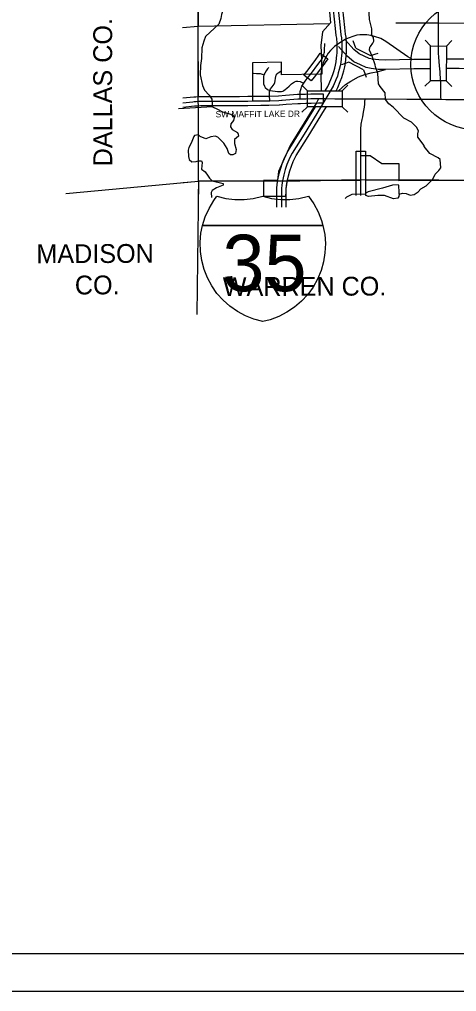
# Model space of a CAD drawing. Extents: x -1403959 to 81668, y -1400582 to 11018.
# Drawn here: x 6223 to 6493, y 7241 to 7841 of the extents above; entities that cross this region are included whole.
import ezdxf

# ---------------------------------------------------------------- set-up
doc = ezdxf.new("R2010")
doc.units = 0
for name, color, linetype in [('tdCiAirportTxt', 7, 'Continuous'), ('tdCiCityCartoShort', 7, 'Continuous'), ('tdCiCityStreetTxt', 7, 'Continuous'), ('tdCiCoBndryTxt', 7, 'Continuous'), ('tdCiRRCL', 7, 'Continuous'), ('tdCiRROwnerTxt', 7, 'Continuous'), ('tdCiSectLine', 7, 'Continuous'), ('tdCiSectNmbr', 7, 'Continuous'), ('tdCiSectTwpRng', 7, 'Continuous'), ('tdCoCityStreetMajor', 7, 'Continuous'), ('tdCoCityStreetMinor', 7, 'Continuous'), ('tdCoClipBndry', 7, 'Continuous'), ('tdCoDivCarto', 7, 'Continuous'), ('tdCoPriCL', 7, 'Continuous'), ('tdCoSecRdNmbr', 7, 'Continuous'), ('tdCoSectLine', 7, 'Continuous'), ('tdCoSectNmbr', 7, 'Continuous'), ('tdCoSurfAsphalt', 7, 'Continuous'), ('tdCoSurfBitum', 7, 'Continuous'), ('tdCoSurfEarth', 7, 'Continuous'), ('tdCoSurfGravel', 7, 'Continuous')]:
    doc.layers.add(name, color=color, linetype=linetype)

msp = doc.modelspace()

# ---------------------------------------------------------------- linework, layer by layer
at = {"layer": 'tdCiAirportTxt'}
for points in [[(6411.84, 7796.77), (6413.48, 7799.47), (6414.4, 7801.3), (6415.87, 7804.73), (6416.69, 7806.83), (6417.22, 7808.66), (6417.82, 7810.71), (6418.3, 7812.72), (6418.62, 7814.76), (6418.88, 7816.87), (6419.16, 7818.84), (6419.21, 7820.13), (6419.24, 7821.55), (6419.23, 7822.21), (6419.34, 7826.04), (6419.01, 7829.21), (6418.78, 7830.96), (6418.29, 7835.25), (6415.77, 7858.39)], [(6418.61, 7796.78), (6419.66, 7798.84), (6421.24, 7802.53), (6422.19, 7804.96), (6422.8, 7807.05), (6423.43, 7809.22), (6424, 7811.6), (6424.37, 7813.95), (6424.64, 7816.1), (6424.95, 7818.32), (6425.01, 7819.97), (6425.04, 7821.52), (6425.04, 7822.14), (6425.15, 7826.26), (6424.78, 7829.89), (6424.54, 7831.67), (6424.06, 7835.89), (6421.54, 7859)], [(6382.03, 7725.01), (6382.03, 7733.47), (6382.13, 7736.79), (6382.33, 7739.11), (6382.79, 7741.85), (6383.57, 7745.77), (6384.5, 7749.2), (6385.63, 7752.51), (6386.91, 7755.53), (6387.79, 7757.47), (6389.06, 7759.88), (6396.39, 7771.64), (6405.88, 7787.02)], [(6387.84, 7725), (6387.84, 7733.38), (6387.93, 7736.45), (6388.1, 7738.39), (6388.5, 7740.81), (6389.22, 7744.44), (6390.05, 7747.5), (6391.05, 7750.43), (6392.22, 7753.19), (6393.01, 7754.91), (6394.1, 7756.99), (6401.32, 7768.58), (6411.48, 7785.03), (6412.68, 7787.03)]]:
    msp.add_lwpolyline(points, dxfattribs=at)
at = {"layer": 'tdCiCityCartoShort'}
for points in [[(6418.65, 7858.67), (6421.18, 7835.55), (6421.66, 7831.29), (6421.9, 7829.53), (6422.25, 7826.13), (6422.13, 7822.15), (6422.14, 7821.51), (6422.11, 7820.03), (6422.06, 7818.56), (6421.76, 7816.46), (6421.49, 7814.33), (6421.15, 7812.14), (6420.62, 7809.94), (6420.01, 7807.83), (6419.44, 7805.87), (6418.55, 7803.61), (6417.03, 7800.04), (6415.48, 7796.99)], [(6416.87, 7799.6), (6409, 7786.52), (6398.85, 7770.09), (6391.58, 7758.41), (6390.4, 7756.16), (6389.57, 7754.33), (6388.34, 7751.45), (6387.27, 7748.33), (6386.39, 7745.08), (6385.64, 7741.31), (6385.21, 7738.73), (6385.03, 7736.6), (6384.93, 7733.4), (6384.93, 7727.88), (6384.93, 7724.98)]]:
    msp.add_lwpolyline(points, dxfattribs=at)
at = {"layer": 'tdCiCityStreetTxt'}
for p, q in [((6476.92, 7824.5), (6473.49, 7827.96)), ((6476.79, 7803.05), (6476.92, 7824.5)), ((6476.92, 7824.5), (6486.66, 7824.44)), ((6486.66, 7824.44), (6486.53, 7802.99)), ((6486.66, 7824.44), (6490.13, 7827.86)), ((6400.94, 7796.76), (6397.49, 7800.2)), ((6422.38, 7796.78), (6425.83, 7800.23)), ((6476.79, 7803.05), (6473.32, 7799.63)), ((6486.53, 7802.99), (6476.79, 7803.05)), ((6486.53, 7802.99), (6486.53, 7802.99)), ((6486.53, 7802.99), (6489.96, 7799.53)), ((6400.94, 7796.76), (6422.38, 7796.78)), ((6400.95, 7787.01), (6400.94, 7796.76)), ((6422.38, 7796.78), (6422.39, 7787.04)), ((6400.95, 7787.01), (6397.5, 7783.56)), ((6422.39, 7787.04), (6400.95, 7787.01)), ((6400.95, 7787.01), (6400.95, 7787.01)), ((6422.39, 7787.04), (6425.84, 7783.59))]:
    msp.add_line(p, q, dxfattribs=at)
at = {"layer": 'tdCiCoBndryTxt'}
for points in [[(6324.01, 7789.48), (6330.3, 7790.09), (6331.09, 7790.16), (6332.35, 7790.27), (6333.61, 7790.35), (6333.71, 7790.35)], [(6333.71, 7790.35), (6333.72, 7790.35)], [(6333.72, 7790.35), (6334, 7790.36)], [(6334, 7790.36), (6334.87, 7790.38), (6340.71, 7790.38), (6348.1, 7790.37), (6359.01, 7790.48), (6364.2, 7790.53), (6367.1, 7790.54)], [(6367.1, 7790.54), (6372.12, 7790.57), (6377.07, 7790.61), (6377.79, 7790.64), (6383.41, 7790.88), (6387.7, 7791.31), (6395.02, 7791.77), (6395.3, 7791.77), (6396.56, 7791.77)], [(6433.9, 7741.86), (6433.87, 7748.92), (6433.88, 7756.72)]]:
    msp.add_lwpolyline(points, dxfattribs=at)
at = {"layer": 'tdCiRRCL'}
msp.add_line((6373.87, 7731.77), (6387.68, 7731.88), dxfattribs=at)
for points in [[(6411.41, 7879.71), (6415.21, 7838.79), (6410.32, 7833.22), (6409.21, 7824.84), (6409.55, 7815.92), (6409.88, 7807.12), (6385.03, 7806.58), (6385.04, 7814.41), (6367.1, 7813.99), (6367.1, 7790.54), (6377.07, 7790.61), (6383.41, 7790.88), (6385.02, 7791.04), (6387.7, 7791.31), (6395.02, 7791.77), (6396.56, 7791.77), (6399.88, 7791.93), (6403.16, 7791.99), (6407.8, 7792), (6407.73, 7791.85), (6406.6, 7789.32), (6390.28, 7763.02), (6383.19, 7747), (6382.41, 7741.71), (6373.85, 7741.52), (6373.87, 7731.77)], [(6387.68, 7731.88), (6387.75, 7734.68), (6387.88, 7736.33), (6388.19, 7738.91), (6388.51, 7740.78), (6388.71, 7741.72), (6433.9, 7741.75), (6433.91, 7756.87), (6439.59, 7756.88), (6446.88, 7752.02), (6457.28, 7751.94), (6457.24, 7741.46), (6578.95, 7741.63), (6579.15, 7731.96)]]:
    msp.add_lwpolyline(points, dxfattribs=at)
at = {"layer": 'tdCiRROwnerTxt'}
for points in [[(6402.79, 7806.97), (6408.02, 7813.81), (6408.87, 7814.94), (6409.55, 7815.9)], [(6396.56, 7791.77), (6399.88, 7791.93), (6403.16, 7791.99), (6407.8, 7792)], [(6433.9, 7741.75), (6433.9, 7741.86)], [(6433.98, 7732.24), (6433.95, 7734.37), (6433.95, 7735.82), (6433.92, 7738.29), (6433.9, 7741.05), (6433.9, 7741.75)]]:
    msp.add_lwpolyline(points, dxfattribs=at)
at = {"layer": 'tdCiSectLine'}
for points in [[(6403.33, 7802.91), (6398.72, 7806.43), (6400.49, 7808.74), (6405.71, 7815.56), (6406.52, 7816.64), (6407.18, 7817.57), (6408.85, 7819.94), (6413.59, 7816.6), (6411.92, 7814.23), (6411.24, 7813.26), (6411.19, 7813.2), (6410.35, 7812.07), (6410.33, 7812.04), (6405.1, 7805.21), (6403.33, 7802.91)], [(6324.01, 7792.4), (6330.81, 7793.05), (6330.83, 7793.05), (6332.09, 7793.16), (6332.16, 7793.17), (6332.18, 7793.17), (6333.44, 7793.24), (6333.53, 7793.25), (6334.79, 7793.28), (6334.87, 7793.28), (6340.71, 7793.28), (6340.72, 7793.28), (6348.09, 7793.27), (6358.98, 7793.38), (6358.99, 7793.38), (6364.17, 7793.43), (6364.18, 7793.43), (6372.1, 7793.48), (6377, 7793.51), (6383.2, 7793.77), (6387.41, 7794.19), (6387.51, 7794.2), (6387.52, 7794.2), (6394.83, 7794.66), (6395.02, 7794.67), (6395.02, 7794.67), (6396.49, 7794.67), (6399.73, 7794.83), (6399.83, 7794.83), (6403.11, 7794.89), (6403.15, 7794.89), (6407.79, 7794.9), (6410.69, 7794.91), (6410.71, 7789.11), (6407.81, 7789.1), (6403.19, 7789.08), (6399.97, 7789.03), (6396.7, 7788.87), (6396.56, 7788.86), (6396.56, 7788.86), (6395.11, 7788.86), (6387.94, 7788.41), (6383.7, 7787.99), (6383.6, 7787.98), (6383.53, 7787.98), (6377.2, 7787.71), (6377.1, 7787.71), (6372.14, 7787.67), (6372.13, 7787.67), (6364.22, 7787.62), (6359.04, 7787.58), (6348.13, 7787.47), (6348.1, 7787.47), (6348.1, 7787.47), (6340.71, 7787.48), (6334.91, 7787.48), (6333.74, 7787.45), (6332.56, 7787.38), (6331.36, 7787.27), (6324.01, 7786.57)], [(6431.07, 7732.22), (6431.05, 7734.33), (6431.05, 7734.37), (6431.05, 7735.8), (6431.01, 7738.25), (6431.01, 7738.27), (6431, 7741.04), (6431, 7741.04), (6430.97, 7748.91), (6430.97, 7748.92), (6430.97, 7748.93), (6430.98, 7756.73), (6430.99, 7759.63), (6436.79, 7759.62), (6436.79, 7756.72), (6436.77, 7748.93), (6436.8, 7741.07), (6436.82, 7738.31), (6436.85, 7735.86), (6436.85, 7735.82), (6436.85, 7734.39), (6436.88, 7732.23)]]:
    msp.add_lwpolyline(points, dxfattribs=at)
at = {"layer": 'tdCiSectNmbr'}
for points in [[(6396.56, 7791.77), (6396.46, 7793.55), (6396.42, 7794.93), (6396.46, 7795.62), (6396.54, 7796.31), (6396.66, 7796.99), (6396.83, 7797.67), (6397.03, 7798.33), (6397.27, 7798.98), (6397.56, 7799.61), (6397.88, 7800.23), (6398.25, 7800.87), (6398.65, 7801.49), (6399.07, 7802.09), (6399.53, 7802.68), (6401.47, 7805.25), (6402.78, 7806.97)], [(6407.8, 7792), (6408.92, 7792.01), (6412.61, 7791.99), (6417.8, 7791.91), (6427.5, 7791.8), (6436.49, 7791.8), (6449.36, 7791.82), (6462.21, 7791.59), (6482.39, 7791.7), (6483.25, 7791.66)], [(6433.92, 7771.11), (6433.93, 7773.18), (6433.98, 7774.26), (6434.05, 7775.24), (6434.16, 7776.23), (6434.31, 7777.21), (6434.48, 7778.19), (6434.69, 7779.15), (6435.09, 7780.81), (6435.63, 7783.67), (6436.08, 7786.82), (6436.27, 7788.49), (6436.36, 7789.98), (6436.49, 7791.8)], [(6483.25, 7791.66), (6483.38, 7791.66), (6486.25, 7791.54), (6496.24, 7791.54), (6499.15, 7791.42), (6502.05, 7791.28), (6504.58, 7791.11), (6507.11, 7790.97), (6509.64, 7790.86), (6510.86, 7790.86), (6519.03, 7790.86), (6531.05, 7790.82)], [(6433.88, 7756.72), (6433.88, 7756.81), (6433.95, 7764.73), (6433.92, 7769.28), (6433.92, 7771.11)]]:
    msp.add_lwpolyline(points, dxfattribs=at)
at = {"layer": 'tdCiSectTwpRng'}
for points in [[(6481.89, 7838.74), (6481.59, 7875.18), (6481.59, 7883.85), (6481.72, 7885.37), (6481.93, 7886.6), (6482.36, 7887.98)], [(6455.56, 7838.77), (6460.76, 7838.76)], [(6460.76, 7838.76), (6481.89, 7838.74)], [(6482.05, 7817.62), (6481.87, 7819.98), (6481.9, 7838.64), (6481.89, 7838.74)], [(6481.89, 7838.74), (6536.74, 7838.59), (6539.26, 7838.58), (6548.54, 7838.57), (6559.78, 7838.56)], [(6409.56, 7815.91), (6409.63, 7816.02), (6410, 7816.62), (6410.34, 7817.25), (6410.64, 7817.9), (6410.89, 7818.56), (6411.11, 7819.24), (6411.28, 7819.93), (6411.42, 7820.62), (6411.51, 7821.33), (6411.55, 7821.84), (6411.6, 7825.97)], [(6482.89, 7807.09), (6482.78, 7808.6), (6482.48, 7812.26), (6482.05, 7817.62)], [(6377.17, 7811.28), (6376.4, 7810.29), (6375.59, 7809.21), (6374.71, 7807.69), (6374.16, 7806.62), (6373.96, 7805.49), (6373.8, 7803.99), (6373.78, 7802.63), (6373.94, 7801.18), (6374.41, 7799.78), (6374.89, 7798.94), (6376.27, 7797.69), (6377.8, 7797.08), (6379.42, 7796.79), (6380.98, 7796.56), (6382.55, 7796.38), (6383.73, 7796.36), (6384.93, 7796.45), (6385.74, 7796.65), (6386.45, 7796.99), (6387.24, 7797.53), (6388.22, 7798.42), (6389.64, 7799.62), (6391.16, 7801.05), (6392.3, 7801.91), (6393, 7802.29), (6394.02, 7802.68), (6395.04, 7802.77), (6396.58, 7802.61), (6397.35, 7802.23), (6398.65, 7801.49)], [(6367.38, 7807.64), (6367.6, 7807.63)], [(6367.6, 7807.63), (6369.47, 7807.53), (6371.76, 7807.42), (6372.96, 7807.15), (6374.16, 7806.62)], [(6377.79, 7790.64), (6377.6, 7793.65), (6377.53, 7796.17), (6377.61, 7796.65), (6377.8, 7797.08), (6378.19, 7798.05), (6379.14, 7799.25), (6379.8, 7800.03), (6380.53, 7801), (6380.89, 7801.91), (6381.15, 7802.87), (6381.21, 7804.55), (6381.37, 7805.55), (6381.77, 7806.54), (6382.23, 7807.19), (6382.97, 7807.99), (6384.53, 7808.98)], [(6483.38, 7791.66), (6483.34, 7792.87), (6483.32, 7796.9), (6483.33, 7800.43), (6483.26, 7802.31), (6482.9, 7807.01), (6482.89, 7807.09)]]:
    msp.add_lwpolyline(points, dxfattribs=at)
at = {"layer": 'tdCoCityStreetMajor'}
for points in [[(6333.98, 7900.91), (6333.65, 7836.58)], [(6323.98, 7835.81), (6333.65, 7836.58)], [(6333.65, 7836.58), (6414.8, 7838.36)], [(6333.68, 7793.24), (6333.65, 7836.58)], [(6333.72, 7741.13), (6333.68, 7787.43)], [(6324.24, 7740.24), (6333.72, 7741.13)], [(6333.72, 7741.13), (6333.6, 7731.49)], [(6333.72, 7741.13), (6396.34, 7741.37), (6421.98, 7741.74)], [(6436.77, 7741.9), (6457.21, 7741.82)]]:
    msp.add_lwpolyline(points, dxfattribs=at)
at = {"layer": 'tdCoCityStreetMinor'}
for points in [[(6252.02, 7733.46), (6333.72, 7741.13)], [(6333.72, 7741.13), (6332.76, 7658.95)], [(6436.77, 7741.9), (6457.21, 7741.82)]]:
    msp.add_lwpolyline(points, dxfattribs=at)
at = {"layer": 'tdCoClipBndry'}
msp.add_lwpolyline([(6772.45, 7982.6), (6773.16, 7838.81), (6797.35, 7838.44), (6797.21, 7788.96), (6796.4, 7741.34), (6748.6, 7741.24), (6723.92, 7741.45), (6627.16, 7741.7), (6530.1, 7741.53), (6433.87, 7741.91), (6421.98, 7741.74), (6396.34, 7741.37), (6333.72, 7741.13), (6333.65, 7836.58), (6334.16, 7936.62)], dxfattribs=at)
at = {"layer": 'tdCoDivCarto'}
for points in [[(6476.87, 7816.2), (6466.4, 7816.08), (6449.18, 7815.73), (6445.03, 7815.82), (6440.9, 7816.3), (6441.22, 7816.25), (6439.03, 7816.75), (6432.82, 7819.68), (6429.57, 7822.35), (6424.43, 7828.07)], [(6476.83, 7810.4), (6466.53, 7810.27), (6449.19, 7809.93), (6444.62, 7810.03), (6440.23, 7810.54), (6437.19, 7811.22), (6433.6, 7812.8), (6429.63, 7814.78), (6425.56, 7818.13), (6420.08, 7824.23)], [(6535.85, 7816.42), (6514.47, 7816.27), (6494.65, 7816.36), (6486.61, 7816.32)], [(6537.33, 7810.62), (6514.57, 7810.47), (6494.64, 7810.56), (6486.58, 7810.52)]]:
    msp.add_lwpolyline(points, dxfattribs=at)
at = {"layer": 'tdCoPriCL'}
for points in [[(6465.74, 7816.06), (6462.83, 7817.76), (6449.3, 7827.28), (6446.22, 7828.98), (6442.34, 7830.4), (6440.03, 7830.96), (6437.69, 7831.29), (6435.32, 7831.38), (6433.2, 7831.28), (6431.35, 7831.03), (6429.54, 7830.57), (6426.15, 7829.28), (6424.16, 7828.37), (6421.59, 7826.9)], [(6421.59, 7826.9), (6417.73, 7824.08), (6415.18, 7821.7), (6413.66, 7819.93), (6412.01, 7817.09), (6410.73, 7814.06), (6409.8, 7810.77), (6409.28, 7807.34), (6409.33, 7796.76)], [(6420.09, 7796.8), (6424.48, 7800.61), (6427.74, 7802.85), (6432.47, 7805.34), (6436.34, 7806.88), (6440.36, 7807.98), (6444.56, 7808.76), (6449.19, 7809.93)]]:
    msp.add_lwpolyline(points, dxfattribs=at)
at = {"layer": 'tdCoSectLine'}
for points in [[(5665.9, 10336.72), (9631.74, 10336.72), (9631.74, 7241.43), (5665.9, 7241.43)], [(5689.11, 10313.51), (9608.52, 10313.51), (9608.52, 7264.65), (5689.11, 7264.65)]]:
    msp.add_lwpolyline(points, close=True, dxfattribs=at)
at = {"layer": 'tdCoSurfAsphalt'}
msp.add_circle((6505.12, 7813.11), 40.33, dxfattribs=at)
at = {"layer": 'tdCoSurfBitum'}
for points in [[(6457.47, 7733.16), (6459.61, 7733.61), (6461.9, 7733.45), (6464.34, 7732.52), (6466.79, 7732.82), (6469.24, 7734.49), (6470.93, 7736.47), (6474.14, 7738.14), (6478.28, 7742.24), (6479.82, 7745.45), (6481.96, 7747.73), (6483.19, 7749.25), (6482.75, 7754.44), (6481.68, 7755.52), (6476.5, 7758.13), (6473, 7762.57), (6473, 7763.03), (6469.05, 7768.24), (6469.06, 7770.37), (6469.52, 7772.05), (6468.31, 7774.5), (6465.11, 7777.57), (6460.39, 7779.87), (6453.84, 7786.77), (6451.25, 7788.76), (6449.12, 7791.37), (6448.99, 7795.49), (6445.79, 7799.47), (6444.88, 7801.16), (6444.29, 7807.57), (6442.93, 7811.55), (6442.78, 7812.92), (6440.97, 7818.27), (6439.3, 7821.79), (6439.46, 7823.77), (6439.92, 7824.08), (6441.3, 7826.21), (6441.92, 7827.43), (6441.77, 7829.72), (6440.71, 7831.1), (6440.72, 7835.07), (6439.22, 7840.72), (6438.22, 7861.04)], [(6351.13, 7850.52), (6349.59, 7849.15), (6347.89, 7843.97), (6347.58, 7841.37), (6346.35, 7837.86), (6338.07, 7830.26), (6336.99, 7827.52), (6335.91, 7823.24), (6335.58, 7816.68), (6334.95, 7812.41), (6334.78, 7806.6), (6336.13, 7800.03), (6337.5, 7797.28), (6340.39, 7794.06), (6341.91, 7791.61), (6342.35, 7787.03)], [(6342.35, 7787.03), (6321.46, 7785.79)], [(6342.35, 7787.03), (6345.55, 7785.49), (6348.6, 7783.8), (6353.79, 7782.41), (6355.01, 7781.64), (6355.77, 7780.42), (6355.3, 7778.58), (6353.77, 7776.45), (6353.45, 7774.62), (6354.52, 7772.94), (6357.72, 7771.09), (6358.33, 7770.18), (6358.48, 7768.95), (6356.02, 7766.82), (6356.02, 7764.23), (6356.92, 7760.56), (6356.6, 7758.12), (6354.92, 7757.36), (6353.55, 7757.37), (6352.48, 7758.13), (6351.42, 7761.34), (6349.45, 7764.56), (6345.64, 7768.24), (6343.97, 7768.85), (6341.37, 7768.41), (6338.31, 7767.2), (6334.8, 7768.74), (6333.74, 7769.66), (6331.29, 7769.21), (6330.83, 7768.6), (6329.29, 7764.48), (6327.9, 7761.89), (6327.29, 7760.21), (6327.58, 7756.24), (6328.03, 7754.41), (6329.55, 7753.03), (6332.3, 7753.17), (6333.53, 7753.62), (6335.51, 7753.62), (6335.97, 7752.55), (6335.65, 7748.42), (6337.93, 7746.89), (6339.76, 7744.29), (6340.51, 7742.91), (6342.19, 7741.38), (6348.9, 7739.67), (6348.9, 7738.6), (6344.77, 7736.94), (6342.17, 7735.42), (6341.55, 7734.2), (6341.68, 7730.95)], [(6453.52, 7738.67), (6447.25, 7736.71), (6438.39, 7734.45), (6437.16, 7733.85), (6436.85, 7733.08)], [(6457.47, 7733.16), (6457.63, 7734.38), (6457.34, 7738.35), (6456.88, 7738.81), (6453.52, 7738.67)], [(6436.85, 7733.08), (6428.45, 7732.81), (6425.09, 7731.14), (6424.3, 7730.52)], [(6454.1, 7730.27), (6448.46, 7732.28), (6444.34, 7732.29), (6438.68, 7731.7), (6437, 7732.32), (6436.85, 7733.08)], [(6457.47, 7733.16), (6457.32, 7731.63), (6456.7, 7730.72), (6454.1, 7730.27)]]:
    msp.add_lwpolyline(points, dxfattribs=at)
at = {"layer": 'tdCoSurfEarth'}
for p, q in [((6430.75, 7823.08), (6429.2, 7827.71)), ((6430.75, 7823.08), (6439.86, 7818.52)), ((6439.86, 7818.52), (6444.58, 7820.1)), ((6426.5, 7814.39), (6421.88, 7812.85)), ((6435.6, 7809.84), (6426.5, 7814.39)), ((6435.6, 7809.84), (6437.14, 7805.21))]:
    msp.add_line(p, q, dxfattribs=at)
at = {"layer": 'tdCoSurfGravel'}
msp.add_line((6336.86, 7713.75), (6409.87, 7713.75), dxfattribs=at)
for points in [[(6373.39, 7654.5), (6367.94, 7655.95), (6362.69, 7658.02), (6357.72, 7660.7), (6353.1, 7663.93), (6348.89, 7667.68), (6345.14, 7671.9), (6341.91, 7676.52), (6339.24, 7681.49), (6337.16, 7686.74), (6335.72, 7692.19), (6334.92, 7697.78), (6334.77, 7703.42), (6335.29, 7709.04), (6336.24, 7713.75), (6337.95, 7719.13), (6340.28, 7724.27), (6343.19, 7729.1), (6345.16, 7731.78), (6350.64, 7730.45), (6356.24, 7729.77), (6361.88, 7729.75), (6367.49, 7730.38), (6373.39, 7731.78), (6378.87, 7730.45), (6384.47, 7729.77), (6390.11, 7729.75), (6395.72, 7730.38), (6401.62, 7731.78), (6404.86, 7727.16), (6407.53, 7722.19), (6409.61, 7716.95), (6410.54, 7713.75), (6411.61, 7708.21), (6412.03, 7702.59), (6411.79, 7696.95), (6410.89, 7691.38), (6409.35, 7685.95), (6407.19, 7680.74), (6404.43, 7675.82), (6401.12, 7671.25), (6397.3, 7667.1), (6393.02, 7663.42), (6388.35, 7660.27), (6383.33, 7657.68), (6378.05, 7655.69)], [(6336.24, 7713.75), (6337.95, 7719.13), (6340.28, 7724.27), (6343.19, 7729.1), (6345.16, 7731.78), (6350.64, 7730.45), (6356.24, 7729.77), (6361.88, 7729.75), (6367.49, 7730.38), (6373.39, 7731.78), (6378.87, 7730.45), (6384.47, 7729.77), (6390.11, 7729.75), (6395.72, 7730.38), (6401.62, 7731.78), (6404.86, 7727.16), (6407.53, 7722.19), (6409.61, 7716.95), (6410.54, 7713.75)], [(6373.39, 7654.5), (6367.94, 7655.95), (6362.69, 7658.02), (6357.72, 7660.7), (6353.1, 7663.93), (6348.89, 7667.68), (6345.14, 7671.9), (6341.91, 7676.52), (6339.24, 7681.49), (6337.16, 7686.74), (6335.72, 7692.19), (6334.92, 7697.78), (6334.77, 7703.42), (6335.29, 7709.04), (6336.24, 7713.75), (6410.54, 7713.75), (6411.61, 7708.21), (6412.03, 7702.59), (6411.79, 7696.95), (6410.89, 7691.38), (6409.35, 7685.95), (6407.19, 7680.74), (6404.43, 7675.82), (6401.12, 7671.25), (6397.3, 7667.1), (6393.02, 7663.42), (6388.35, 7660.27), (6383.33, 7657.68), (6378.05, 7655.69)]]:
    msp.add_lwpolyline(points, close=True, dxfattribs=at)

# ---------------------------------------------------------------- texts
at = {"layer": 'tdCoSecRdNmbr'}
for s, rotation, p in [('DALLAS CO.', 90.0414, (6280.53, 7750.25)), ('MADISON', 0.219, (6233.77, 7690.51)), ('CO.', 0.219, (6257.5, 7671.25)), ('WARREN CO.', 0.219, (6348.75, 7670.24))]:
    msp.add_text(s, height=11.607, rotation=rotation, dxfattribs=at).set_placement(p)
at = {"layer": 'tdCoSectNmbr'}
msp.add_text('SW MAFFIT LAKE DR', height=3.8691, rotation=0.34059, dxfattribs=at).set_placement((6344.33, 7780.43))
at = {"layer": 'tdCoSurfGravel'}
msp.add_text('35', height=34.822, dxfattribs=at).set_placement((6348.56, 7673.26))

doc.saveas('drawing.dxf')
